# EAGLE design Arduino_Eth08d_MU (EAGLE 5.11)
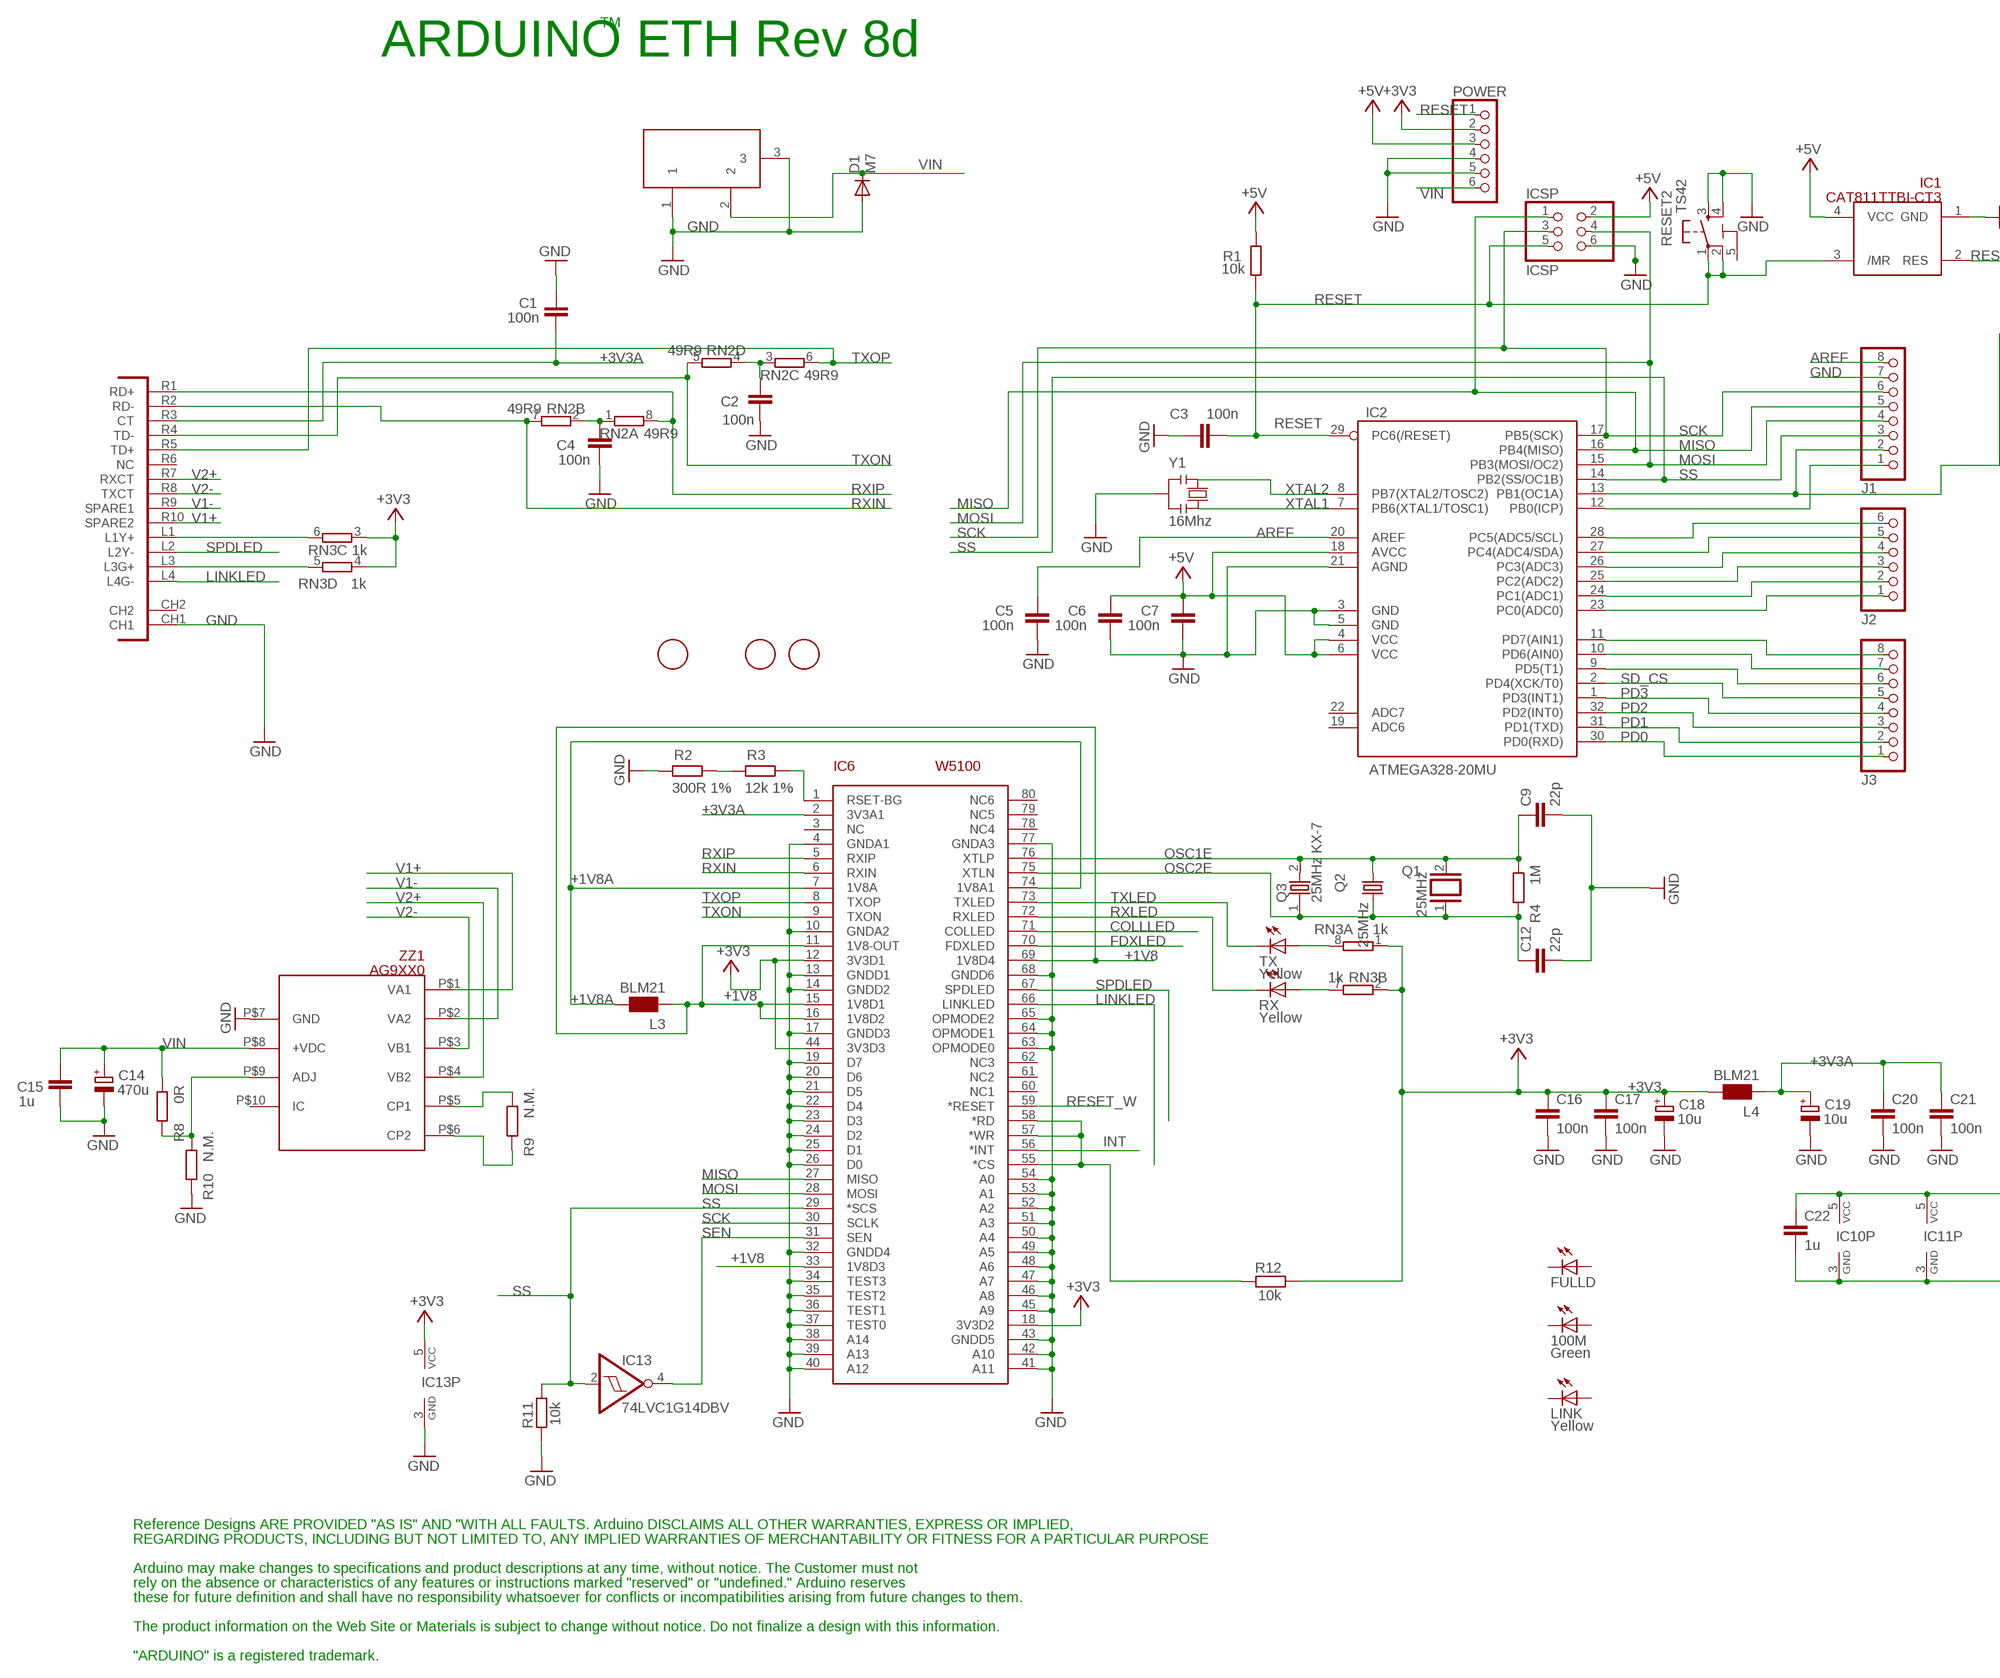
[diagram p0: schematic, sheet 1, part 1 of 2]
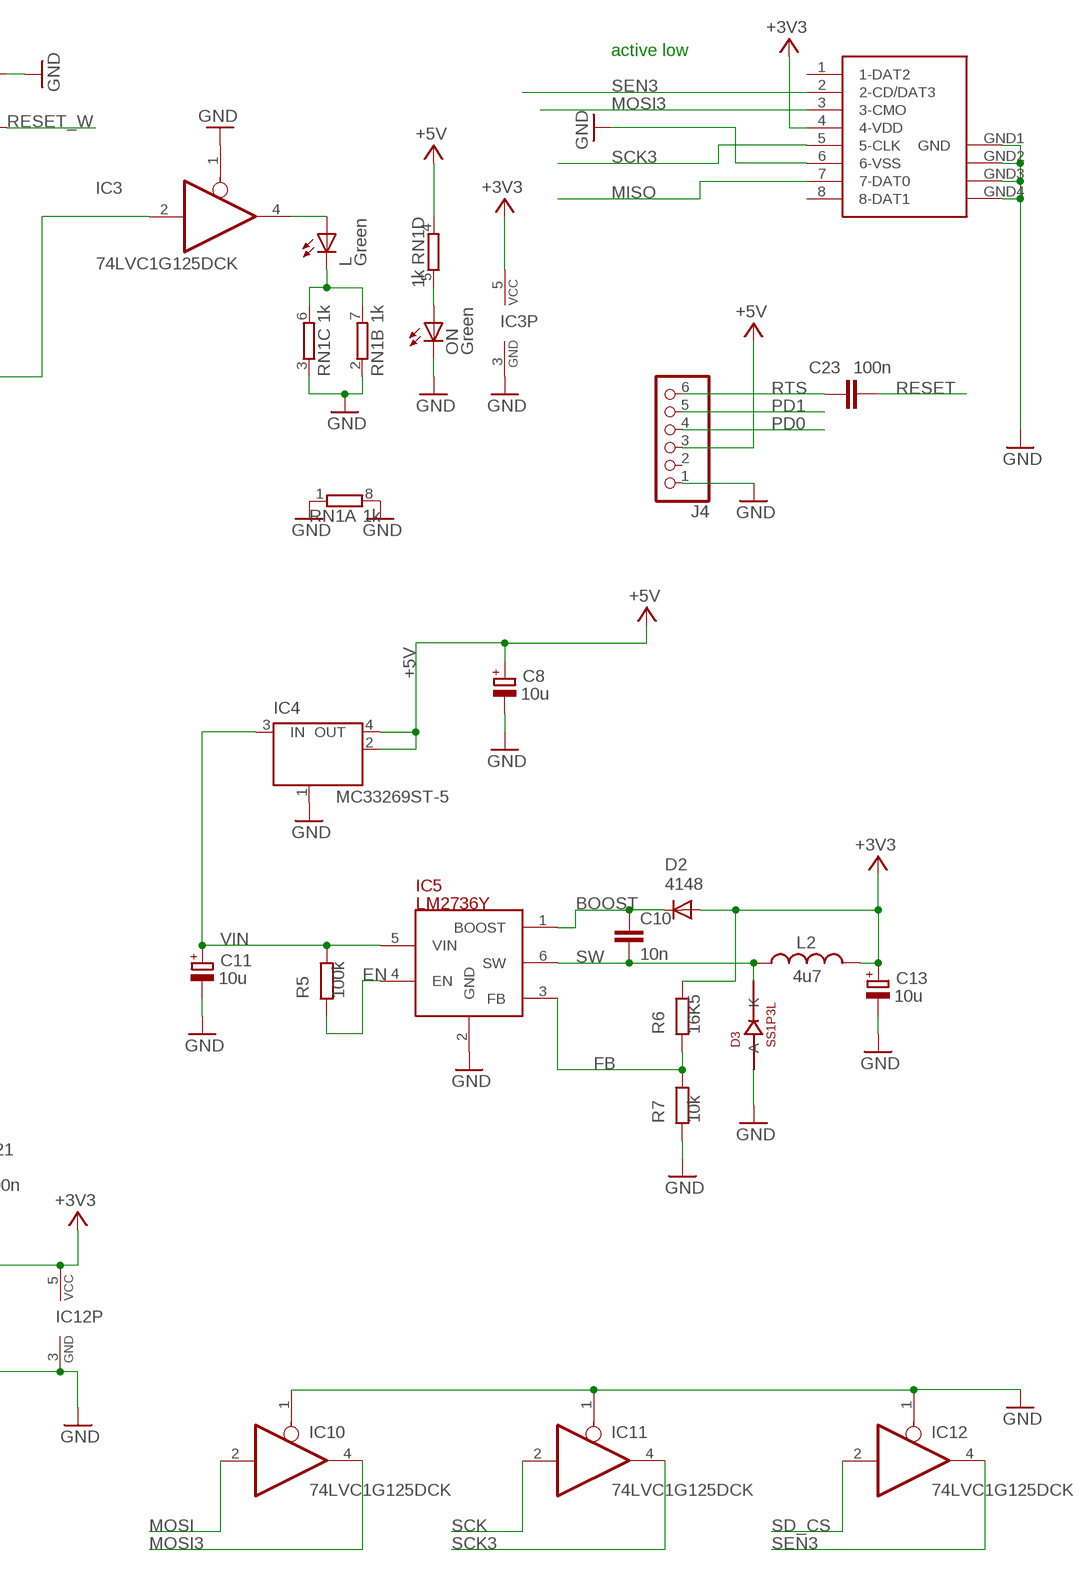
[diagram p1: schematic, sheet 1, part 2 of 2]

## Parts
100M  Green  LEDCHIPLED_0805  [CHIPLED_0805]
C1  100n  C-EUC0603  [C0603-ROUND]
C2  100n  C-EUC0603  [C0603-ROUND]
C3  100n  C-EUC0603  [C0603-ROUND]
C4  100n  C-EUC0603  [C0603-ROUND]
C5  100n  C-EUC0603  [C0603-ROUND]
C6  100n  C-EUC0603  [C0603-ROUND]
C7  100n  C-EUC0603  [C0603-ROUND]
C8  10u  CPOL-EUSMCB  [SMC_B]
C9  22p  C-EUC0603  [C0603-ROUND]
C10  10n  C-EUC0603  [C0603-ROUND]
C11  10u  CPOL-EUSMCB  [SMC_B]
C12  22p  C-EUC0603  [C0603-ROUND]
C13  10u  CPOL-EUSMCB  [SMC_B]
C14  470u  CPOL-EUD  [PANASONIC_D]
C15  1u  C-EUC0603  [C0603-ROUND]
C16  100n  C-EUC0603  [C0603-ROUND]
C17  100n  C-EUC0603  [C0603-ROUND]
C18  10u  CPOL-EUSMCB  [SMC_B]
C19  10u  CPOL-EUSMCB  [SMC_B]
C20  100n  C-EUC0603  [C0603-ROUND]
C21  100n  C-EUC0603  [C0603-ROUND]
C22  1u  C-EUC0603  [C0603-ROUND]
C23  100n  C-EUC0603  [C0603-ROUND]
D1  M7  DIODE-SMB  [SMB]
D2  4148  DIODE-MINIMELF  [MINIMELF]
D3  SS1P3L  [DO220AAL]
FULLD  LEDCHIPLED_0805  [CHIPLED_0805]
IC1  CAT811TTBI-CT3  STM812  [SOT143]
IC2  ATMEGA328-20MU  MEGA8-MI  [MLF32]
IC3  74LVC1G125DCK  [SC70-5]
IC4  MC33269ST-5  MC33269ST-3.3T3  [SOT223]
IC5  LM2736Y  [SOT23-6]
IC6  W5100  [SQFP-S-10X10-80]
IC10  74LVC1G125DCK  [SC70-5]
IC11  74LVC1G125DCK  [SC70-5]
IC12  74LVC1G125DCK  [SC70-5]
IC13  74LVC1G14DBV  [SOT23-5]
ICSP  ICSP  PINHD-2X3  [2X03]
J1  PINHD-1X8  [1X08]
J2  PINHD-1X6  [1X06]
J3  PINHD-1X8  [1X08]
J4  PINHD-1X6  [1X06]
L  Green  LEDCHIPLED_0805  [CHIPLED_0805]
L2  4u7  L-USSRR0604  [SRR0604]
L3  BLM21  WE-CBF_0805  [0805]
L4  BLM21  WE-CBF_0805  [0805]
LINK  Yellow  LEDCHIPLED_0805  [CHIPLED_0805]
ON  Green  LEDCHIPLED_0805  [CHIPLED_0805]
POWER  PINHD-1X6  [1X06]
Q1  25MHz  XTAL/S  [QS]
Q2  25MHz  CRYSTALHC49UP  [HC49UP]
Q3  25MHz KX-7  KX-7  [CRYSTAL3.2X2.5]
R1  10k  R-EU_0603-RND  [R0603-ROUND]
R2  300R 1%  R-EU_0603-RND  [R0603-ROUND]
R3  12k 1%  R-EU_0603-RND  [R0603-ROUND]
R4  1M  R-EU_0603-RND  [R0603-ROUND]
R5  100k  R-EU_0603-RND  [R0603-ROUND]
R6  16K5  R-EU_0603-RND  [R0603-ROUND]
R7  10k  R-EU_0603-RND  [R0603-ROUND]
R8  0R  R-EU_0603-RND  [R0603-ROUND]
R9  N.M.  R-EU_0603-RND  [R0603-ROUND]
R10  N.M.  R-EU_0603-RND  [R0603-ROUND]
R11  10k  R-EU_0603-RND  [R0603-ROUND]
R12  10k  R-EU_R0603  [R0603-ROUND]
RESET2  TS42  [TS42]
RN1  1k  4R-NCAY16  [CAY16]
RN2  49R9  4R-NCAY16  [CAY16]
RN3  1k  4R-NCAY16  [CAY16]
RX  Yellow  LEDCHIPLED_0805  [CHIPLED_0805]
TX  Yellow  LEDCHIPLED_0805  [CHIPLED_0805]
U$1  POE-RJ45  [POE-RJ45]
U$2  FIDUCIALMOUNT  [FIDUCIA-MOUNT]
U$4  FIDUCIALMOUNT  [FIDUCIA-MOUNT]
U$5  FIDUCIALMOUNT  [FIDUCIA-MOUNT]
X1  DC21MMX  [DC-21MM]
X2  SDCARD-15TW-8821  [SDCARD-15TW-8821]
Y1  16Mhz  RESONATORMU  [RESONATOR]
ZZ1  AG9XX0  [AG9000]

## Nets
+1V8 [power]: IC6.11(1V8-OUT) IC6.15(1V8D1) IC6.16(1V8D2) IC6.33(1V8D3) IC6.69(1V8D4) L3.1
+1V8A [power]: IC6.7(1V8A) IC6.74(1V8A1) L3.2
+3V3 [power]: C13.+ C16.1 C17.1 C18.+ C22.1 D2.A IC3.5(VCC) IC6.12(3V3D1) IC6.18(3V3D2) IC6.44(3V3D3) IC10.5(VCC) IC11.5(VCC) IC12.5(VCC) IC13.5(VCC) L2.P$2 L4.2 POWER.2 R6.1 R12.2 RN3.1 RN3.2 RN3.3 RN3.4 X2.4(4-VDD)
+3V3A [power]: C1.1 C19.+ C20.1 C21.1 IC6.2(3V3A1) L4.1 U$1.R3(CT)
+5V [power]: C6.1 C7.1 C8.+ IC1.4(VCC) IC2.4(VCC) IC2.6(VCC) IC2.18(AVCC) IC4.2(OUT) IC4.4(OUT) ICSP.2 J4.3 POWER.3 R1.2 RN1.4
AREF: C5.1 IC2.20(AREF) J1.8
BOOST: C10.1 D2.C IC5.1(BOOST)
COLLLED: IC6.71(COLLED)
EN: IC5.4(EN) R5.2
FB: IC5.3(FB) R6.2 R7.1
FDXLED: IC6.70(FDXLED)
GND [power]: C1.2 C2.1 C3.2 C4.1 C5.2 C6.2 C7.2 C8.- C9.2 C11.- C12.2 C13.- C14.- C15.1 C16.2 C17.2 C18.- C19.- C20.2 C21.2 C22.2 D1.A D3.P$2(A) IC1.1(GND) IC2.3(GND) IC2.5(GND) IC2.21(AGND) IC3.1(OE) IC3.3(GND) IC4.1(GND/ADJ) IC5.2(GND) IC6.4(GNDA1) IC6.10(GNDA2) IC6.13(GNDD1) IC6.14(GNDD2) IC6.17(GNDD3) IC6.19(D7) IC6.20(D6) IC6.21(D5) IC6.22(D4) IC6.23(D3) IC6.24(D2) IC6.25(D1) IC6.26(D0) IC6.32(GNDD4) IC6.34(TEST3) IC6.35(TEST2) IC6.36(TEST1) IC6.37(TEST0) IC6.38(A14) IC6.39(A13) IC6.40(A12) IC6.41(A11) IC6.42(A10) IC6.43(GNDD5) IC6.45(A9) IC6.46(A8) IC6.47(A7) IC6.48(A6) IC6.49(A5) IC6.50(A4) IC6.51(A3) IC6.52(A2) IC6.53(A1) IC6.54(A0) IC6.63(OPMODE0) IC6.64(OPMODE1) IC6.65(OPMODE2) IC6.68(GNDD6) IC6.77(GNDA3) IC10.1(OE) IC10.3(GND) IC11.1(OE) IC11.3(GND) IC12.1(OE) IC12.3(GND) IC13.3(GND) ICSP.6 J1.7 J4.1 ON.C POWER.4 POWER.5 R2.2 R7.2 R10.2 R11.1 RESET2.3 RESET2.4 RN1.1 RN1.2 RN1.3 RN1.8 U$1.CH1 X1.1 X1.3 X2.6(6-VSS) X2.GND1(GND) X2.GND2(GND1) X2.GND3(GND2) X2.GND4(GND3) Y1.2 ZZ1.P$7(GND)
INT: IC6.56(*INT)
LINKLED: IC6.66(LINKLED) U$1.L4(L4G-)
MISO: IC2.16(PB4(MISO)) IC6.27(MISO) ICSP.1 J1.5 X2.7(7-DAT0)
MOSI: IC2.15(PB3(MOSI/OC2)) IC6.28(MOSI) IC10.2(I) ICSP.4 J1.4
MOSI3: IC10.4(O) X2.3(3-CMO)
N$1: IC3.4(O) L.A
N$2: RN3.5 U$1.L3(L3G+)
N$3: RN3.6 U$1.L1(L1Y+)
N$4: IC2.13(PB1(OC1A)) IC3.2(I) J1.2
N$5: L.C RN1.6 RN1.7
N$8: ON.A RN1.5
N$9: RN3.8 TX.A
N$10: C2.2 RN2.3 RN2.4
N$13: IC2.9(PD5(T1)) J3.6
N$14: IC2.10(PD6(AIN0)) J3.7
N$15: IC2.11(PD7(AIN1)) J3.8
N$16: IC2.23(PC0(ADC0)) J2.1
N$17: IC2.24(PC1(ADC1)) J2.2
N$18: IC2.25(PC2(ADC2)) J2.3
N$19: IC2.26(PC3(ADC3)) J2.4
N$20: IC2.27(PC4(ADC4/SDA)) J2.5
N$21: IC2.28(PC5(ADC5/SCL)) J2.6
N$22: RN3.7 RX.A
N$29: C4.2 RN2.1 RN2.2
N$30: R2.1 R3.2
N$31: IC6.1(RSET-BG) R3.1
N$32: R9.1 ZZ1.P$5(CP1)
N$33: R9.2 ZZ1.P$6(CP2)
N$34: R8.2 R10.1 ZZ1.P$9(ADJ)
N$36: IC6.55(*CS) IC6.57(*WR) IC6.58(*RD) R12.1
OSC1E: C9.1 IC6.76(XTLP) Q1.2 Q2.1 Q3.2 R4.1
OSC2E: C12.1 IC6.75(XTLN) Q1.1 Q2.2 Q3.1 R4.2
PD0: IC2.30(PD0(RXD)) J3.1 J4.4
PD1: IC2.31(PD1(TXD)) J3.2 J4.5
PD2: IC2.32(PD2(INT0)) J3.3
PD3: IC2.1(PD3(INT1)) J3.4
RESET: C3.1 C23.1 IC1.3(/MR) IC2.29(PC6(/RESET)) ICSP.5 POWER.1 R1.1 RESET2.1 RESET2.2
RESET_W: IC1.2(RES) IC6.59(*RESET)
RTS: C23.2 J4.6
RXIN: IC6.6(RXIN) RN2.7 U$1.R2(RD-)
RXIP: IC6.5(RXIP) RN2.8 U$1.R1(RD+)
RXLED: IC6.72(RXLED) RX.C
SCK: IC2.17(PB5(SCK)) IC6.30(SCLK) IC11.2(I) ICSP.3 J1.6
SCK3: IC11.4(O) X2.5(5-CLK)
SD_CS: IC2.2(PD4(XCK/T0)) IC12.2(I) J3.5
SEN: IC6.31(SEN) IC13.4(O)
SEN3: IC12.4(O) X2.2(2-CD/DAT3)
SPDLED: IC6.67(SPDLED) U$1.L2(L2Y-)
SS: IC2.14(PB2(SS/OC1B)) IC6.29(*SCS) IC13.2(I) J1.3 R11.2
SW [power]: C10.2 D3.P$1(K) IC5.6(SW) L2.P$1
TXLED: IC6.73(TXLED) TX.C
TXON: IC6.9(TXON) RN2.5 U$1.R4(TD-)
TXOP: IC6.8(TXOP) RN2.6 U$1.R5(TD+)
V1+ [VIN]: U$1.R10(SPARE2) ZZ1.P$1(VA1)
V1- [VIN]: U$1.R9(SPARE1) ZZ1.P$2(VA2)
V2+ [VIN]: U$1.R7(RXCT) ZZ1.P$4(VB2)
V2- [VIN]: U$1.R8(TXCT) ZZ1.P$3(VB1)
VIN [VIN]: C11.+ C14.+ C15.2 D1.C IC4.3(IN) IC5.5(VIN) POWER.6 R5.1 R8.1 X1.2 ZZ1.P$8(+VDC)
WOL/IO: IC2.12(PB0(ICP)) J1.1
XTAL1: IC2.7(PB6(XTAL1/TOSC1)) Y1.3
XTAL2: IC2.8(PB7(XTAL2/TOSC2)) Y1.1
Unconnected: 100M.A 100M.C FULLD.A FULLD.C IC2.19(ADC6) IC2.22(ADC7) IC6.3(NC) IC6.60(NC1) IC6.61(NC2) IC6.62(NC3) IC6.78(NC4) IC6.79(NC5) IC6.80(NC6) J4.2 LINK.A LINK.C U$1.CH2 U$1.R6(NC) X2.1(1-DAT2) X2.8(8-DAT1) ZZ1.P$10(IC)

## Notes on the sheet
- TM
- ARDUINO ETH Rev 8d
- active low
- Reference Designs ARE PROVIDED "AS IS" AND "WITH ALL FAULTS. Arduino DISCLAIMS ALL OTHER WARRANTIES, EXPRESS OR IMPLIED,
- REGARDING PRODUCTS, INCLUDING BUT NOT LIMITED TO, ANY IMPLIED WARRANTIES OF MERCHANTABILITY OR FITNESS FOR A PARTICULAR PURPOSE
- Arduino may make changes to specifications and product descriptions at any time, without notice. The Customer must not
- rely on the absence or characteristics of any features or instructions marked "reserved" or "undefined." Arduino reserves
- these for future definition and shall have no responsibility whatsoever for conflicts or incompatibilities arising from future changes to them.
- The product information on the Web Site or Materials is subject to change without notice. Do not finalize a design with this information.
- "ARDUINO" is a registered trademark.

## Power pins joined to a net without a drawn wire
5-GND: RESET2.5(5-GND)

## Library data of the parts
100M FULLD L LINK ON RX TX = led:LED: LED
C1-C7 C9 C10 C12 C15-C17 C20-C23 = SmartPrj:C-EU: CAPACITOR, European symbol
C8 C11 C13 C14 C18 C19 = rcl:CPOL-EU: POLARIZED CAPACITOR, European symbol
D1 D2 = diode:DIODE-: DIODE
D3 = SmartPrj:SS1P3L
IC1 = SmartPrj:STM812
IC2 = idii:MEGA8: MICROCONTROLLER 8 Kbytes FLASH 1 kbytes SRAM 512 bytes EEPROM USART 6-channel 10 bit ADC 2-channel 8 bit ADC Source: avr.lbr
IC3 IC10-IC12 = 74xx-little-us:74*1G125: Single Bus Buffer Gate with 3-State Output
IC4 = linear:MC33269ST*: Adjustable Output Low Dropout Voltage Regulator 800 mA Source: http://www.onsemi.com/pub/Collateral/MC33269-D.PDF
IC5 = SmartPrj:LM2736Y
IC6 = SmartPrj:W5100
IC13 = 74xx-little-de:74*1G14: Single Schmitt-Trigger Inverter Gate
ICSP = pinhead:PINHD-2X3: PIN HEADER
J1 J3 = pinhead:PINHD-1X8: PIN HEADER
J2 J4 POWER = pinhead:PINHD-1X6: PIN HEADER
L2 = SmartPrj:L-US: INDUCTOR, American symbol
L3 L4 = wuerth-elektronik:WE-CBF: SMD EMI Suppression Ferrite Beads
Q1 = special:XTAL/S: CRYSTAL
Q2 = crystal:CRYSTAL: CRYSTAL
Q3 = SmartPrj:KX-7
R1-R12 = SmartPrj:R-EU_: RESISTOR, European symbol
RESET2 = st-mod v1.4:TS42: TS42 Dongnan Electronics Tact switch VDC 12V - 50mA
RN1-RN3 = resistor-dil:4R-N: Array Chip Resistor Source: RS Component / Phycomp
U$1 = SmartPrj:POE-RJ45
U$2 U$4 U$5 = SmartPrj:FIDUCIALMOUNT
X1 = powersupply:DC21MM
X2 = st-mod v1.3:SDCARD-15TW-8821: SD Card SDCARD 15TW 8821
Y1 = Nano_MySMD2:RESONATOR
ZZ1 = SmartPrj:AG9XX0: PoE module

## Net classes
0 default: width 0.152 mm, drill 0.61 mm, clearance 0.152 mm
1 power: width 0.152 mm, drill 0.61 mm, clearance 0.152 mm
2 VIN: width 0.61 mm, drill 0.61 mm, clearance 0.305 mm

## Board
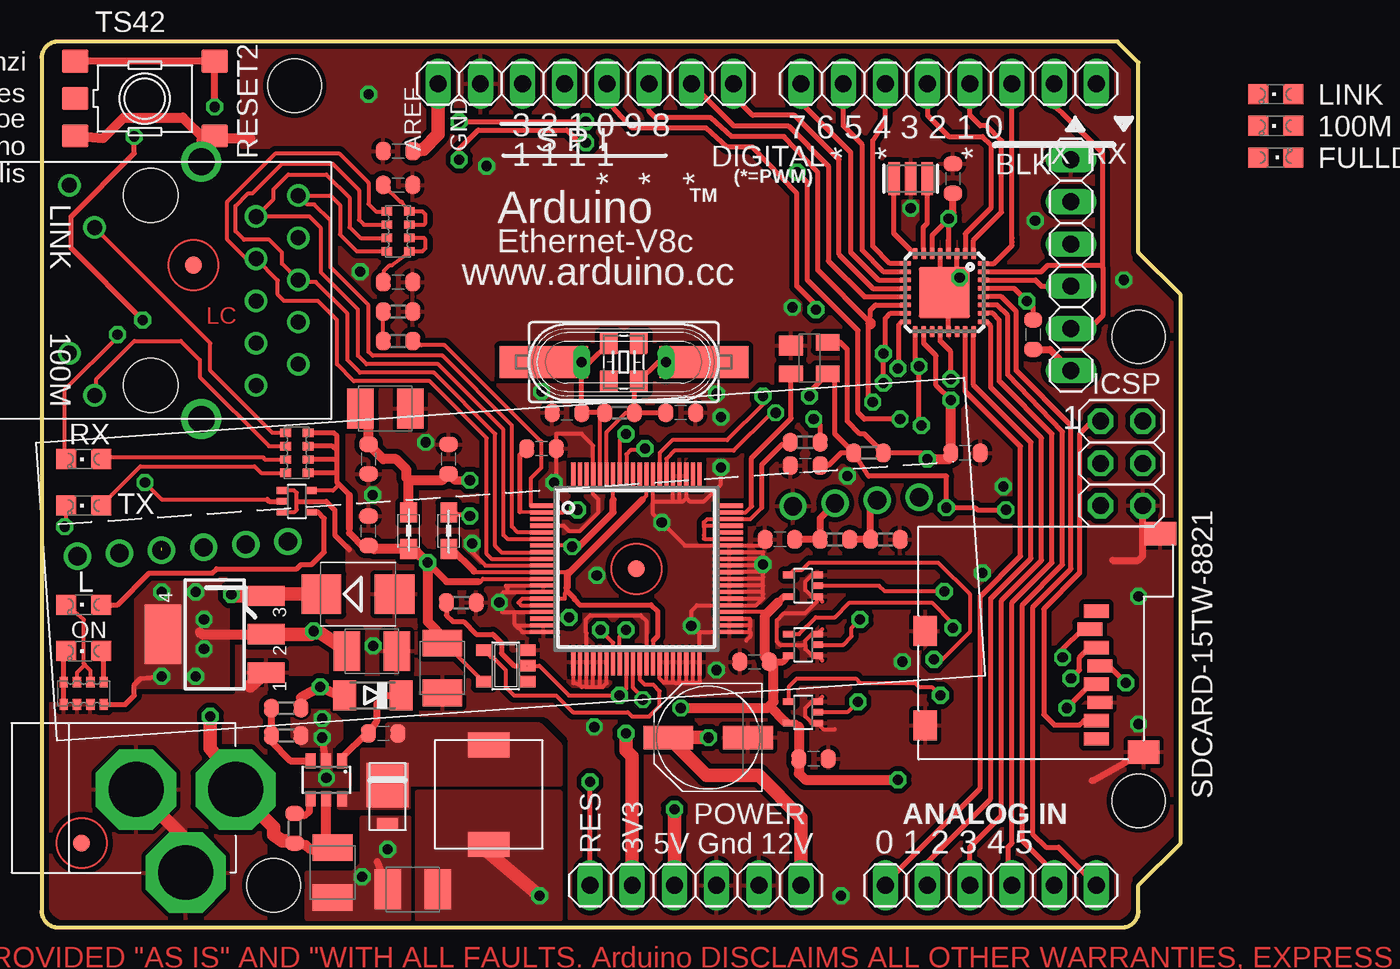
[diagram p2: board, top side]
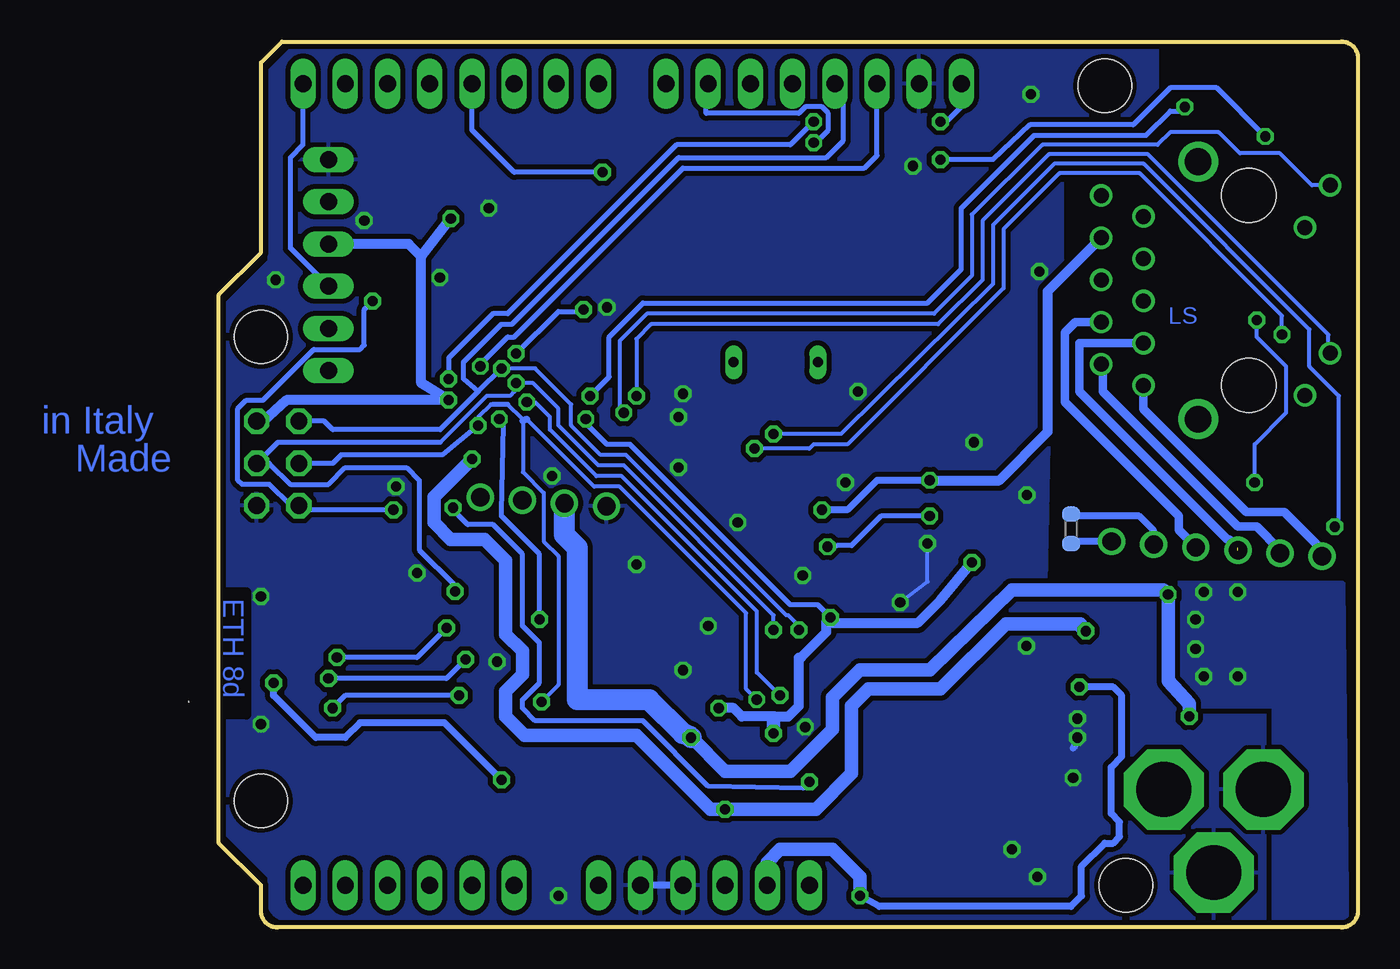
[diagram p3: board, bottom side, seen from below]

Size 68.58 x 53.34 mm. Coordinates in mm from the lower left corner, seen from the top.
Outline: 66.04,2.54 68.58,5.08 68.58,38.1 66.04,40.64 66.04,52.07 64.77,53.34 1,53.34 arc90 0,52.34 0,1 arc90 1,0 65.04,0 arc90 66.04,1 66.04,2.54
Copper layers (1*16): Top 0.035mm / dielectric 1.5mm / Bottom 0.035mm
Design rules "ArduinoDEF": minimum track width 6mil, minimum drill 12mil, track to track 5mil, track to pad 5mil, pad to pad 5mil, via to via 5mil, smd to smd 4mil, copper to edge 10mil, drill to drill 6mil, minimum pad ring 8mil, minimum via ring 8mil, stop-mask expansion 0mil, vias tented up to drill 0mil, thermal gap 10mil
Holes 3.2 mm at 66.04,35.56 66.04,7.62 15.24,50.67 13.97,2.54
bRestrict: area 66.9,12.8 to 69,20.2

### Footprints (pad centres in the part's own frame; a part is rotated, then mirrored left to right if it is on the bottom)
CHIPLED_0805 = smd 1.2 x 1.2: A 0,-1.05; C 0,1.05
C0603-ROUND = smd 0.898 x 1.1: 1 -0.889,0; 2 0.889,0
SMC_B = smd 1.6 x 2.4: + -1.5,0; - 1.5,0
PANASONIC_D = smd 3 x 1.4: + 2.4,0; - -2.4,0
SMB = smd 2.4 x 2.4: A 2.2,0; C -2.2,0
MINIMELF = smd 1.4 x 1.8: A 1.7,0; C -1.7,0
DO220AAL = smd 2.667 x 2.54: P$1 -0.7,0 | smd 0.762 x 1.27: P$2 1.65,0
SOT143 = smd 1.2 x 1.44: 1 -0.75,-1.1 | smd 1 x 1.44: 2 0.95,-1.1; 3 0.95,1.1; 4 -0.95,1.1
MLF32 = smd 0.7 x 0.3: 1 -2.35,1.75; 2 -2.35,1.25; 3 -2.35,0.75; 4 -2.35,0.25; 5 -2.35,-0.25; 6 -2.35,-0.75; 7 -2.35,-1.25; 8 -2.35,-1.75; 17 2.35,-1.75; 18 2.35,-1.25; 19 2.35,-0.75; 20 2.35,-0.25; 21 2.35,0.25; 22 2.35,0.75; 23 2.35,1.25; 24 2.35,1.75 | smd 0.3 x 0.7: 9 -1.75,-2.35; 10 -1.25,-2.35; 11 -0.75,-2.35; 12 -0.25,-2.35; 13 0.25,-2.35; 14 0.75,-2.35; 15 1.25,-2.35; 16 1.75,-2.35; 25 1.75,2.35; 26 1.25,2.35; 27 0.75,2.35; 28 0.25,2.35; 29 -0.25,2.35; 30 -0.75,2.35; 31 -1.25,2.35; 32 -1.75,2.35 | smd 3.1 x 3.1: PAD 0,0
SC70-5 = smd 0.4 x 0.7: 1 -0.65,-0.85; 2 0,-0.85; 3 0.65,-0.85; 4 0.65,0.85; 5 -0.65,0.85
SOT223 = smd 1.219 x 2.235: 1 -2.311,-3.099; 2 0,-3.099; 3 2.311,-3.099 | smd 3.6 x 2.2: 4 0,3.099
SOT23-6 = smd 0.6 x 0.9: 1 -0.95,-1.15; 2 0,-1.15; 3 0.95,-1.15; 4 0.95,1.15; 5 0,1.15; 6 -0.95,1.15
SQFP-S-10X10-80 = smd 0.25 x 1.6: 1 -3.8,-5.6; 2 -3.4,-5.6; 3 -3,-5.6; 4 -2.6,-5.6; 5 -2.2,-5.6; 6 -1.8,-5.6; 7 -1.4,-5.6; 8 -1,-5.6; 9 -0.6,-5.6; 10 -0.2,-5.6; 11 0.2,-5.6; 12 0.6,-5.6; 13 1,-5.6; 14 1.4,-5.6; 15 1.8,-5.6; 16 2.2,-5.6; 17 2.6,-5.6; 18 3,-5.6; 19 3.4,-5.6; 20 3.8,-5.6; 41 3.8,5.6; 42 3.4,5.6; 43 3,5.6; 44 2.6,5.6; 45 2.2,5.6; 46 1.8,5.6; 47 1.4,5.6; 48 1,5.6; 49 0.6,5.6; 50 0.2,5.6; 51 -0.2,5.6; 52 -0.6,5.6; 53 -1,5.6; 54 -1.4,5.6; 55 -1.8,5.6; 56 -2.2,5.6; 57 -2.6,5.6; 58 -3,5.6; 59 -3.4,5.6; 60 -3.8,5.6 | smd 1.6 x 0.25: 21 5.6,-3.8; 22 5.6,-3.4; 23 5.6,-3; 24 5.6,-2.6; 25 5.6,-2.2; 26 5.6,-1.8; 27 5.6,-1.4; 28 5.6,-1; 29 5.6,-0.6; 30 5.6,-0.2; 31 5.6,0.2; 32 5.6,0.6; 33 5.6,1; 34 5.6,1.4; 35 5.6,1.8; 36 5.6,2.2; 37 5.6,2.6; 38 5.6,3; 39 5.6,3.4; 40 5.6,3.8; 61 -5.6,3.8; 62 -5.6,3.4; 63 -5.6,3; 64 -5.6,2.6; 65 -5.6,2.2; 66 -5.6,1.8; 67 -5.6,1.4; 68 -5.6,1; 69 -5.6,0.6; 70 -5.6,0.2; 71 -5.6,-0.2; 72 -5.6,-0.6; 73 -5.6,-1; 74 -5.6,-1.4; 75 -5.6,-1.8; 76 -5.6,-2.2; 77 -5.6,-2.6; 78 -5.6,-3; 79 -5.6,-3.4; 80 -5.6,-3.8
SOT23-5 = smd 0.69 x 0.99: 1 -0.95,-1.29; 2 0,-1.29; 3 0.95,-1.29; 4 0.95,1.3; 5 -0.95,1.3
2X03 = drill 1.016 octagon: 1 -2.54,-1.27; 2 -2.54,1.27; 3 0,-1.27; 4 0,1.27; 5 2.54,-1.27; 6 2.54,1.27
1X08 = drill 1.016 long: 1 -8.89,0; 2 -6.35,0; 3 -3.81,0; 4 -1.27,0; 5 1.27,0; 6 3.81,0; 7 6.35,0; 8 8.89,0
1X06 = drill 1.016 long: 1 -6.35,0; 2 -3.81,0; 3 -1.27,0; 4 1.27,0; 5 3.81,0; 6 6.35,0
SRR0604 = smd 1.5 x 2.5: P$1 3,0; P$2 -3,0
0805 = smd 1.2 x 1: 1 -1.1,0; 2 1.1,0
QS = drill 0.61 long: 1 -2.54,0; 2 2.54,0
HC49UP = smd 5.334 x 1.93: 1 -4.826,0; 2 4.826,0
CRYSTAL3.2X2.5 = smd 1.3 x 1.1: 1 -1.15,-0.9; 2 1.15,0.9; 3 1.15,-0.9; 4 -1.15,0.9
R0603-ROUND = smd 0.898 x 1.1: 1 -0.889,0; 2 0.889,0
TS42 = smd 1.6 x 1.4: 1 -4.2,2.25; 2 4.2,2.25; 3 -4.2,-2.25; 4 4.2,-2.25; 5 -4.2,0
CAY16 = smd 0.5 x 0.65: 1 -1.2,-0.675; 2 -0.4,-0.675; 3 0.4,-0.675; 4 1.2,-0.675; 5 1.2,0.675; 6 0.4,0.675; 7 -0.4,0.675; 8 -1.2,0.675
POE-RJ45 = drill 1.6 round: CH1 13.94,7.75; CH2 13.94,-7.75 | drill 0.9 round: L1 7.51,-6.325; L2 5.99,-3.785; L3 7.51,3.785; L4 5.99,6.325; R1 19.77,5.715; R2 17.23,4.445; R3 19.77,3.175; R4 17.23,1.905; R5 19.77,0.635; R6 17.23,-0.635; R7 19.77,-1.905; R8 17.23,-3.175; R9 19.77,-4.445; R10 17.23,-5.715 | hole 3.25: 10.89,5.715; 10.89,-5.715
FIDUCIA-MOUNT = smd 1.016 x 1.016: P$1 0,0
DC-21MM = drill 3.302 pad 4.826 octagon: 1 -5.08,-3.353; 2 -0.076,-6.35; 3 -0.076,-0.356
SDCARD-15TW-8821 = smd 0.8 x 1.5: 1 0,0; 2 1.1,-0.4; 3 2.2,0; 4 3.3,0.2; 5 4.4,0; 6 5.5,0.2; 7 6.6,0; 8 7.7,0 | smd 1.4 x 1.9: GND1 -4.66,3.85; GND2 8.49,2.85 | smd 1.8 x 1.4: GND3 1.19,-10.3; GND4 6.89,-10.3
RESONATOR = smd 0.7 x 2: 1 -1,0; 2 0,0; 3 1,0
AG9000 = drill 1.1 round: P$1 0,0; P$2 2.54,0; P$3 5.08,0; P$4 7.62,0; P$5 10.16,0; P$6 12.7,0; P$7 43.18,0; P$8 45.72,0; P$9 48.26,0; P$10 50.8,0

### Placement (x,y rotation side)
100M  not placed on the board
C1  30.1,28.83 0 top
C2  21.46,44.7 180 top
C3  45.97,27.81 180 top
C4  21.46,38.86 180 top
C5  21.46,46.74 180 top
C6  55.63,28.57 0 top
C7  54.86,45.09 90 top
C8  19.89,16.64 0 top
C9  31.62,30.99 180 top
C10  20.57,11.68 0 top
C11  17.53,3.3 270 top
C12  38.48,30.99 0 top
C13  24.13,15.62 270 top
C14  40.13,11.43 180 top
C15  44.45,23.37 0 top
C16  42.93,16 180 top
C17  19.68,23.88 90 top
C18  22.35,2.29 180 top
C19  20.7,31.24 0 top
C20  19.68,28.19 270 top
C21  24.51,28.19 90 top
C22  46.48,10.16 0 top
C23  59.69,35.69 270 top
D1  19.05,20.07 0 top
D2  19.94,13.97 180 top
D3  20.83,7.87 270 top
FULLD  not placed on the board
IC1  46.23,34.29 270 top
IC2  54.36,38.23 270 top
IC3  15.37,25.65 270 top
IC4  10.41,17.65 90 top
IC5  17.14,8.89 180 top
IC6  35.81,21.59 270 top
IC10  45.85,20.57 90 top
IC11  45.85,12.95 90 top
IC12  45.85,17.02 90 top
IC13  27.94,15.75 90 top
ICSP  65.02,27.94 270 top
J1  32.77,50.8 180 top
J2  57.15,2.54 0 top
J3  54.61,50.8 180 top
J4  61.98,39.88 270 top
L  2.54,19.43 90 top
L2  26.92,8 90 top
L3  24.51,23.88 90 top
L4  22.1,23.88 270 top
LINK  not placed on the board
ON  2.54,16.64 90 top
POWER  39.37,2.54 0 top
Q1  35.05,34.04 180 top
Q2  35.05,34.04 0 top
Q3  35.05,34.04 90 top
R1  49.78,28.57 0 top
R2  21.46,37.08 0 top
R3  21.46,35.31 180 top
R4  34.8,30.99 0 top
R5  15.24,5.97 90 top
R6  14.73,13.21 180 top
R7  14.73,11.56 0 top
R8  47.75,23.37 0 top
R9  17.27,24 270 bottom
R10  50.8,23.37 0 top
R11  25.27,19.56 180 top
R12  45.97,29.21 0 top
RESET2  6.22,49.91 0 top
RN1  2.54,14.1 0 top
RN2  21.46,41.91 90 top
RN3  15.37,28.57 90 top
RX  2.54,28.19 90 top
TX  2.54,25.4 90 top
U$1  -4.32,38.35 0 top
U$2  9.14,39.88 0 top
U$4  35.81,21.59 0 top
U$5  2.41,5.08 0 top
X1  5.33,8.38 90 top
X2  63.5,19.05 270 top
Y1  52.32,45.09 0 top
ZZ1  2.16,22.35 4 top

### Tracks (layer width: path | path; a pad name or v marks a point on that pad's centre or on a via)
+1V8
  Top 0.254: 31.62,20.45 31.59,20.3 31.5,20.07 31.5,19.79 IC6.15 28.93,19.79 28.7,19.56 28.87,19.39 IC6.16 | 36.81,17.26 IC6.33 | 26.04,21.46 26.11,21.39 IC6.11 31.7,21.39 31.75,21.34 | IC6.69 36.41,26 36.16,25.75
  Top 0.305: 31.59,20.3 32.08,19.81 32.08,19.73 32.38,19.43 36.7,19.43 37.08,19.05 37.08,17.53 36.81,17.26
  Top 0.406: 31.62,20.45 31.62,21.34 31.75,21.34 36.16,25.75 | 26.04,21.46 24.64,22.86 24.55,22.86 L3.1
+1V8A  (via drill 0.61)
  Top 0.254: IC6.7 31.62,22.99 31.88,22.99 | 34.41,25.74 IC6.74
  Top 0.305: L3.2 v25.78,24.77
  Top 0.406: 31.88,22.99 v31.94,22.92 32.35,22.92 34.41,24.99 34.41,25.74
  Bottom 0.305: v25.78,24.77 28.7,24.77 30.48,22.99 31.37,22.99 v31.94,22.92
+3V3  (via drill 0.61)
  Top 0.254: IC6.18 31.57,18.59 v31.75,18.67 | IC6.12 26.58,20.99 26.42,20.83 | IC13.5 26.6,14.8 24.64,16.76 24.38,16.74 C13.+ | IC6.44 43.63,18.99 43.56,18.8 | 44.18,14.34 44.18,14.37 44.13,14.41 | IC3.5 17.54,26.3 17.91,26.67
  Top 0.305: v46.48,30.61 46.86,30.23 R12.2 | 44.07,14.22 44.18,14.34 | 44.32,19.56 44.39,19.62 | C16.1 43.88,16.07 | X2.4 64.26,15.75 v65.28,14.73 | 18.53,23.74 18.54,24 | RN3.3 17.51,28.98 17.78,28.7 | 17.78,27.43 17.78,26.8 17.91,26.67 18.54,26.04 | 17.78,27.43 17.78,28.07 | 17.78,28.07 17.78,28.7 | RN3.1 17.72,27.38 17.78,27.43 | RN3.2 17.67,28.18 17.78,28.07 | RN3.4 17.6,29.77 17.78,29.59 17.78,28.7 | 26.29,20.83 26.42,20.83
  Top 0.406: L4.2 21.93,22.9 | 44.07,16 C16.1 44.63,16 IC12.5 | 44.39,19.62 44.69,19.92 IC10.5 | 18.54,24 18.54,26.04 | C17.1 19.41,22.86 18.53,23.74 | 26.29,20.83 24.38,20.83 v23.24,21.97 | 44.77,12.38 44.85,12.3 IC11.5 45.39,12.3 45.59,12.1
  Top 0.61: C13.+ 24.36,17.3 23.24,18.41 v23.24,21.97 22.56,22.65 L4.2 20.02,22.78 C17.1 | v51.56,8.89 45.97,8.89 45.59,9.27 C22.1 45.59,12.1 | 44.32,19.56 43.56,18.8 43.56,16.26 C16.1 | v38.48,13.21 43.69,13.21 43.81,13.34 | 44.07,16 44.07,14.22 44.07,13.59 43.81,13.34 | 43.81,13.34 44.77,12.38 | R6.1 15.62,13.84 v16.76,14.48 17.65,14.1 D2.A
  Top 0.813: v29.97,1.91 26.67,4.7 | POWER.2 35.56,10.29 35.18,10.67 v35.18,11.68
  Bottom 0.305: v31.75,18.67 32.51,19.43 34.16,19.43 43.81,29.08 45.21,29.08 46.48,30.35 v46.48,30.61
  Bottom 0.406: v16.76,14.48 14.73,14.48 14.22,13.97 14.22,10.29 14.86,9.65 14.86,6.86 14.35,6.35 14.35,5.46 14.73,5.08 15.24,5.08 16.64,3.68 16.64,1.91 17.27,1.27 28.83,1.27 v29.97,1.91 | v65.28,14.73 65.28,13.97 62.74,11.43 60.96,11.43 60.07,12.32 54.99,12.32 v51.56,8.89
  Bottom 0.61: v23.24,21.97 25.15,19.68 26.5,18.34 31.67,18.34 v31.75,18.67 32,18.41 32,17.78 33.53,16.26 33.66,16.26 33.66,13.34 34.29,12.7 35.05,12.7 | 35.05,12.7 37.08,12.7 37.59,13.21 v38.48,13.21 | 35.18,12.57 35.05,12.7
  Bottom 0.813: v29.97,1.91 29.97,3.05 31.62,4.7 34.8,4.7 35.56,3.94 POWER.2 | v35.18,11.68 35.18,12.57
  pour Top (no thermals): 31.24,8.13 22.61,8.13 22.61,0.51 31.24,0.51
+3V3A  (via drill 0.61)
  Top 0.254: 28.8,25.02 31.4,24.99 IC6.2 32.5,24.99 32.16,24.99 32.18,25.02
  Top 0.305: 28.8,25.02 28.8,28.47 C1.1
  Top 0.406: v32.26,25.15 32.18,25.02
  Top 0.508: v25.78,26.92 24.89,26.92 C21.1
  Top 0.61: L4.1 22.1,26.95 | 22.1,26.95 24.15,26.95 C21.1 | C19.+ 19.68,30.76 C20.1 20.57,28.19 21.34,28.19 21.97,27.56 21.97,27.07 22.1,26.95
  Bottom 0.406: v32.26,25.15 30.73,25.15 28.96,26.92 v25.78,26.92
  Bottom 0.61: U$1.R3 18.67,38.31 18.67,29.84 21.59,26.92 v25.78,26.92
+5V  (via drill 0.61, 0.61 pad 1.02)
  Top 0.305: IC1.4 48.07,35.24 48.51,34.8 48.51,30.48 49.28,29.72 49.53,29.72 R1.2 52.96,28.57 v53.34,28.19 53.34,28.32 | 54.61,41.41 IC2.4 v54.61,42.67 53.61,41.67 IC2.6 | v7.24,15.11 5.97,14.99 5.59,14.61 5.59,13.97 5.04,13.42 RN1.4 | IC2.18 53.11,35.16 53.85,34.42 53.85,32.64 v54.74,31.75
  Top 0.406: C7.1 54.86,43.05 v54.61,42.67 | 54.61,28.19 C6.1
  Top 0.61: IC4.2 9.65,17.65 9.53,17.78 | C6.1 v54.74,31.75 | v53.34,28.19 54.61,28.19
  Top 0.813: v38.1,7.11 POWER.3 | C8.+ 16.64,17.81 v16.39,17.84 16.2,17.65 IC4.2
  Bottom 0.61: 56.39,40.39 56.39,32.77 v54.74,31.75 64.52,31.75 65.91,30.48 ICSP.2 | 56.39,40.39 v54.61,42.67 | J4.3 57.15,41.15 56.39,40.39
  Bottom 0.813: 16.71,18.29 v16.39,17.84 16.84,18.29 21.21,18.29 25.15,14.35 29.46,14.35 30.48,13.34 30.48,9.27 32.64,7.11 v38.1,7.11 38.99,7.11 43.43,11.56 50.16,11.56 51.31,12.7 51.31,14.22 50.29,15.24 50.29,16.64 51.31,17.65 51.31,22.1 52.58,23.37 54.61,23.37 55.63,24.38 55.63,25.91 v53.34,28.19
  other vias: 9.27,20.19 7.24,20.19 9.27,15.11 9.78,18.54 9.78,16.76
  pour Top (isolate 0.305, no thermals): 5.71,20.95 11.18,21.08 11.18,14.48 5.71,14.48
  pour Bottom (isolate 0.305, no thermals): 0.89,20.7 10.92,20.7 10.92,13.34 5.08,13.34 5.08,-0.64 0.64,-0.64
AREF  (via drill 0.61, 0.61 pad 1.02)
  Top 0.305: v25.15,48.51 v32.77,48.51 | IC2.20 54.11,35.3 54.74,34.67 v54.74,33.02
  Top 0.813: J1.8 23.88,47.75 22.99,46.86 C5.1
  Bottom 0.305: v32.77,48.51 34.16,47.12 41.02,47.12 51.18,36.96 52.07,36.96 54.74,34.29 v54.74,33.02 | v25.15,48.51 24.77,48.51 23.88,49.4 J1.8 | J1.8 23.88,51.18 24,51.31 24,50.93 J1.8
BOOST
  Top 0.305: 18.09,10.09 18.16,10.16 18.16,10.29
  Top 0.406: D2.C 20.7,13.97 20.19,13.46 20.19,12.45 C10.1 19.56,11.68 18.16,10.29 | IC5.1 18.09,10.09
EN
  Top 0.406: R5.2 15.82,6.73 16.13,6.99 16.13,7.67 IC5.4
FB
  Top 0.406: R6.2 R7.1 13.84,11.18 14.98,10.04 IC5.3
GND  (via drill 0.61)
  Top 0.254: IC6.4 31.44,24.19 31.75,23.88 32.41,23.88 33.53,24.99 33.53,25.78 33.21,26.09 IC6.77 33.21,29.02 32.51,29.72 30.99,29.72 C1.2 30.99,26.92 v30.86,26.8 | 28.45,18.99 27.75,18.99 v27.56,19.56 27.81,20.19 28.06,20.19 | 28.45,18.99 IC6.17 | IC6.13 27.96,20.59 27.94,20.57 28.06,20.45 28.06,20.19 | 28.06,20.19 IC6.14 | 28.55,18.19 IC6.19 | 28.55,18.19 28.45,18.29 28.45,18.99 | IC6.20 28.95,17.79 28.55,18.19 | IC6.26 34.01,14.71 33.78,14.48 33.53,14.48 | 32.77,14.48 32.51,14.48 32.41,14.58 | 32.77,14.48 33.27,14.48 | 33.27,14.48 33.53,14.48 | IC6.21 32.01,14.72 32.41,14.58 | 32.41,14.58 IC6.22 | 32.77,14.48 32.81,14.53 IC6.23 32.81,17.73 32.77,17.78 32.77,18.54 33.02,18.8 36.07,18.8 36.41,18.45 IC6.32 | IC6.24 33.21,14.54 33.27,14.48 | IC6.25 33.61,14.56 33.53,14.48 | v39.12,18.16 39.61,17.66 IC6.40 39.62,15.98 39.62,14.73 39.12,14.73 | 37.59,14.73 37.47,14.73 37.21,14.99 IC6.34 | 38.1,14.73 37.59,14.73 | 38.1,14.73 38.35,14.73 | 38.35,14.73 38.86,14.73 | 38.86,14.73 39.12,14.73 | IC6.35 37.61,14.75 37.59,14.73 | IC6.36 38.01,14.82 38.1,14.73 | IC6.37 38.41,14.79 38.35,14.73 | IC6.38 38.81,14.78 38.86,14.73 | IC6.39 39.21,14.83 39.12,14.73 | 42.66,17.79 IC6.41 39.49,17.79 v39.12,18.16 | 42.66,17.79 42.67,17.78 42.67,17.53 42.42,17.27 | 42.66,17.79 42.67,18.29 | 42.67,18.29 42.67,18.54 42.62,18.59 IC6.43 | IC6.42 42.57,18.19 42.67,18.29 | 43.3,22.99 IC6.54 38.73,22.99 v37.34,24.38 36.81,24.91 36.81,25.65 | v43.43,21.84 43.43,22.61 43.42,22.59 IC6.53 | 43.43,20.07 43.43,19.81 43.41,19.79 | 43.41,19.79 43.01,19.39 IC6.45 39.46,19.39 39.12,19.05 v39.12,18.16 | 43.43,20.07 43.43,20.57 | 43.43,20.57 43.43,21.08
  Top 0.254: 43.43,21.08 43.43,21.34 | 43.43,21.34 v43.43,21.84 | IC6.52 43.34,22.19 v43.43,21.84 | IC6.51 43.38,21.79 v43.43,21.84 | IC6.50 43.38,21.39 43.43,21.34 | IC6.49 43.34,20.99 43.43,21.08 | IC6.48 43.42,20.59 43.43,20.57 | IC6.47 43.31,20.19 43.43,20.07 | 43.41,19.79 IC6.46 | 36.81,25.65 IC6.68 | 38.81,25.86 IC6.63 | 38.81,25.86 38.61,25.65 38.35,25.65 | 36.81,25.65 38.1,25.65 | 38.1,25.65 38.35,25.65 | IC6.64 38.41,25.71 38.35,25.65 | IC6.65 38.01,25.74 38.1,25.65 | v40.89,27.69 40.89,26.67 39.88,25.65 39.02,25.65 38.81,25.86 | IC6.10 26.72,21.79 25.91,22.61 v25.91,23.11 | 47,19.62 IC10.1 46.37,19.92 45.97,20.32 45.97,20.83 46.37,21.22 IC10.3 | 47,17.97 IC12.3 46.37,17.67 45.97,17.27 45.97,17.02 | 47,16.07 IC12.1 46.37,16.37 45.97,16.76 45.97,17.02 | 47,13.9 IC11.3 46.37,13.6 45.97,13.21 45.97,12.7 46.37,12.3 IC11.1 47.06,11.94 47.75,11.94 | 46.67,19.62 45.97,18.92 44.7,18.92 44.27,18.49 44.27,17.2 44.45,17.02 45.97,17.02 | IC3.1 15.22,26.3 15.37,26.16 15.37,25.65 15.37,25.15 15.24,25.02 14.53,25.02 IC3.3
  Top 0.305: 18.54,22.73 17.65,23.62 17.65,25.15 17.14,25.65 15.37,25.65 | RN1.1 RN1.8 1.34,16.49 ON.C | IC2.21 54.61,38.45 v55.27,39.12 | IC2.3 55.11,39.28 v55.27,39.12 | IC2.5 54.1,39.24 54.23,39.12 v55.27,39.12
  Top 0.406: X1.3 5.69,8.48 | IC5.2 v16.89,11.43 | C11.- 17.8,1.68 | C18.- 20.22,3.96 | ICSP.6 66.29,22.35 66.04,22.1 64.47,22.1 | 63.25,8.84 X2.GND2
  Top 0.61: RESET2.3 3.72,47.53 4.95,48.77 8.51,48.77 9.78,47.5 9.78,47.53 | 9.78,47.53 RESET2.4 | U$1.CH1 9.62,47.38 9.78,47.53 | 9.78,47.53 12.54,47.53 12.57,47.5
  Top 0.813: X1.1 8.69,5.31 X1.3 5.71,8.33 | 12.57,14.53 IC4.1
  Bottom 0.254: v25.91,23.11 25.91,20.83 v27.56,19.56
  Bottom 0.406: POWER.4 POWER.5 | v16.89,11.43 17.14,10.79
  other vias: 23.11,29.21 19.3,3.05 20.83,4.7 16.89,12.57 17.14,9.02 66.04,12.24 33.43,21.18 40.64,15.49 33.27,12.06 19.96,16.94 57.91,26.54 59.82,42.55 40.89,30.73 66.04,19.94 48.13,1.91 19.94,26.04 19.18,39.5 26.8,45.85 19.68,50.16 30.1,32.26 45.21,37.34 48.51,27.18 52.32,43.31 40.64,32.13 51.82,16 56.64,21.34 65.15,38.99
  pour Bottom (isolate 0.406, no thermals): 14.48,15.24 23.24,15.24 24.51,13.97 24.51,13.72 30.48,13.59 30.48,0.64 14.48,0.76
  pour Top (no thermals): 16,3.3 18.8,3.3 19.3,3.81 19.3,6.6 22.1,6.6 22.1,0.51 16,0.51
  pour Top (no thermals): 15.75,8.51 15.75,9.27 16.89,9.27 16.89,10.92 15.68,10.92 15.11,11.49 15.11,12.95 15.24,13.08 17.4,13.08 18.03,12.45 18.03,11.37 17.59,10.92 17.4,10.92 17.4,9.27 18.54,9.27 18.54,8.51
  pour Top (isolate 0.305, rank 2): 0.51,13.46 5.71,13.46 5.71,20.95 18.41,20.95 18.41,37.34 17.27,37.34 17.27,46.99 12.06,46.99 12.06,53.47 64.26,52.83 65.53,51.56 65.53,40.13 68.07,37.59 68.07,5.59 65.53,3.05 65.53,1.51 arc-90 64.53,0.51 31.75,0.51 31.75,11.43 30.48,12.7 22.86,12.7 22.86,15.24 14.46,15.24 13.46,14.24 13.46,0.51 1.51,0.51 arc-90 0.51,1.51
  pour Bottom (isolate 0.305, rank 2): 17.78,46.99 12.06,46.99 12.06,52.83 64.26,52.83 65.53,51.56 65.53,40.13 68.07,37.59 68.07,5.59 65.53,3.05 65.53,1.51 arc-90 64.53,0.51 1.51,0.51 0.51,1.51 0.76,20.83 18.8,20.7 18.41,37.47 17.78,37.47
LINKLED  (via drill 0.61)
  Top 0.254: IC6.66 37.61,28.22 38.1,28.7 41.66,28.7 43.81,30.86 v44.2,30.99
  Bottom 0.254: v44.2,30.99 44.45,31.24 44.45,35.31 42.8,36.96 25.53,36.96 23.24,39.24 23.24,42.93 18.99,47.12 12.06,47.12 11.3,47.88 8.38,47.88 7.11,46.61 4.7,46.61 2.77,44.68 U$1.L4
MISO  (via drill 0.61)
  Top 0.254: IC6.27 34.41,17.14 v33.66,17.91
  Top 0.305: ICSP.1 63.25,30.48 62.48,29.72 62.48,21.34 60.33,19.18 60.33,12.83 60.96,12.19 62.48,12.19 62.74,12.45 X2.7 | IC2.16 51.8,36.48 51.61,36.27 51.61,33.74 v51.56,33.66
  Bottom 0.254: v33.66,17.91 33.66,18.16 34.29,18.8 34.42,18.8 44.07,28.45 45.59,28.45 47.37,30.23 47.37,31.5 49.53,33.66 v51.56,33.66
  Bottom 0.305: J1.5 31.5,50.42 30.99,49.91 30.99,47.37 32,46.35 40.89,46.35 50.93,36.32 51.56,36.32 53.85,34.04 53.85,33.02 52.96,32.26 | ICSP.1 62.23,30.48 61.72,29.97 55.24,29.97 52.96,32.26 | v51.56,33.66 52.96,32.26
MOSI  (via drill 0.61)
  Top 0.254: v35.18,17.91 34.8,17.53 34.8,16.01 IC6.28 | IC10.2 50.42,20.57 50.76,20.23 v54.36,20.23
  Top 0.305: J1.4 34.04,49.78 35.56,48.13 40.01,48.13 41.27,46.99 42.8,46.99 45.47,44.2 45.47,38.61 46.61,37.47 v46.61,37.21 | v54.36,20.23 54.36,20.32 | IC2.15 51.12,36.98 50.8,36.66 50.8,34.67 v50.67,34.54 v50.67,32.77
  Bottom 0.254: v35.18,17.91 35.18,18.8 44.2,27.81 45.72,27.81 48.13,30.23 48.13,31.24 49.66,32.77 v50.67,32.77 50.8,32.26 51.05,32 52.45,32 55.24,29.21
  Bottom 0.305: v54.36,20.23 54.4,20.61 56.52,22.73 56.52,26.92 57.28,27.69 60.96,27.69 61.98,26.67 64.26,26.67 65.53,27.94 ICSP.4 65.02,29.21 55.24,29.21 | v46.61,37.21 46.74,37.08 48.13,37.08 v50.67,34.54
MOSI3  (via drill 0.61)
  Top 0.254: v53.72,16.13 54.23,16.13 55.88,17.78 55.88,20.07 53.98,21.97 46.23,21.97 45.78,21.52 45.3,21.52 IC10.4
  Top 0.305: X2.3 63.08,16.85 62.48,16.26 62.48,15.49 v61.98,14.99
  Bottom 0.305: v61.98,14.99 54.86,14.99 v53.72,16.13
N$1
  Top 0.305: IC3.4 16.65,25 17.02,24.64 17.02,22.61 16.26,21.84 15.62,21.84 15.37,21.59 10.54,21.59 10.29,21.34 6.48,21.34 4.57,19.43 L.A
N$2
  Top 0.254: U$1.L3 10.16,35.17 10.16,33.53 13.91,29.77 RN3.5
N$3
  Top 0.254: U$1.L1 3.3,32.14 3.3,33.02 5.59,35.31 8.38,35.31 9.53,34.16 9.53,33.15 13.7,28.98 RN3.6
N$4  (via drill 0.61)
  Top 0.254: 13.59,25.78 7.24,25.78 v6.22,26.8
  Top 0.305: IC2.13 49.53,37.98 47.37,40.13 47.37,45.85 44.96,48.26 41.66,48.26 J1.2 | IC3.2 13.72,25.65 13.59,25.78 | v5.59,47.62 5.59,46.61 1.78,42.8 1.78,40.89 v6.1,36.58 | v25.15,46.23 25.15,46.86 26.29,48.01 31.62,48.01 32.38,47.24 v32.77,47.24
  Bottom 0.254: v6.22,26.8 6.22,29.08 4.32,30.99 4.32,33.78 6.1,35.56 6.1,36.07
  Bottom 0.305: v5.59,47.62 8.51,50.55 11.3,50.55 13.53,48.32 19.75,48.32 21.97,46.23 v25.15,46.23 | 6.1,36.07 v6.1,36.58 | J1.2 39.24,50.67 39.24,49.02 33.66,49.02 33.27,49.4 32.26,49.4 31.88,49.02 31.88,48.01 32.64,47.24 v32.77,47.24
N$5
  Top 0.254: L.C 1.65,19.3 2.54,18.54 2.54,15.88 2.6,15.81 | RN1.7 2.14,15.35 2.6,15.81 | RN1.6 2.94,15.47 2.6,15.81
N$8
  Top 0.305: RN1.5 3.74,16.49 ON.A
N$9
  Top 0.254: TX.A 5.95,27.76 12.83,27.76 13.21,27.38 RN3.8
N$10
  Top 0.254: RN2.3 23.01,42.31 23.11,42.42 23.11,42.93 22.93,43.11 RN2.4 21.69,43.69 21.59,43.69 C2.2
N$13
  Top 0.305: J3.6 50.8,48.51 50.04,47.37 50.04,41.02 51.08,39.98 IC2.9
N$14
  Top 0.305: IC2.10 50.69,39.48 49.4,40.77 49.4,47.12 48.26,48.26 J3.7
N$15
  Top 0.305: 45.72,51.21 J3.8 45.72,49.66 48.72,46.66 48.72,40.64 50.38,38.98 IC2.11
N$16
  Top 0.305: J2.1 50.8,2.67 56.52,8.38 56.52,19.94 58.93,22.35 58.93,28.96 55.61,32.28 IC2.23
N$17
  Top 0.305: J2.2 53.34,3.94 57.15,7.75 57.15,19.81 59.56,22.23 59.56,29.21 56.11,32.67 IC2.24
N$18
  Top 0.305: J2.3 55.88,4.83 57.78,6.73 57.78,19.68 60.2,22.1 60.2,29.46 57.15,32.51 57.15,36.2 56.87,36.48 IC2.25
N$19
  Top 0.305: J2.4 58.17,2.79 58.17,4.83 58.42,5.08 58.42,19.56 60.83,21.97 60.83,29.72 57.66,32.89 57.66,36.58 57.26,36.98 IC2.26
N$20
  Top 0.305: J2.5 60.96,3.3 59.05,5.21 59.05,19.43 61.47,21.84 61.47,29.84 58.17,33.27 58.17,36.83 57.52,37.48 IC2.27
N$21
  Top 0.305: J2.6 61.21,4.83 60.45,4.83 59.69,5.59 59.69,19.3 61.98,21.59 61.98,30.23 58.67,33.53 58.67,37.08 57.78,37.98 IC2.28
N$22
  Top 0.254: 3.68,28.19 RX.A 4.1,28.32 13.34,28.32 13.44,28.18 RN3.7
N$29
  Top 0.254: RN2.2 23.01,41.51 23.11,41.4 23.11,40.89 22.93,40.71 RN2.1 22.1,40.64 21.08,39.88 20.95,39.88 20.61,39.54 C4.2
N$30
  Top 0.254: R3.2 R2.1
N$31
  Top 0.254: R3.1 22.86,35.05 24.26,35.05 30.04,29.27 30.1,29.27 30.1,27.69 29.46,27.05 29.46,25.4 29.47,25.39 IC6.1
N$32
  Bottom 0.406: R9.1 17.14,24.77 13.17,24.77 12.29,23.89 ZZ1.P$5
N$33
  Bottom 0.406: ZZ1.P$6 17.15,23.24 R9.2
N$34
  Top 0.406: R8.2 R10.1 49.91,25.33 ZZ1.P$9
N$36
  Top 0.254: 43.36,25.27 42.67,24.59 IC6.58 40.08,24.59 39.88,24.38 39.88,24.13 | 39.9,23.39 IC6.55 | 39.88,23.62 39.9,23.39 | 39.88,24.13 39.88,23.62 | 39.88,23.62 39.88,23.41 39.9,23.39 | IC6.57 39.94,24.19 39.88,24.13
  Top 0.305: 43.36,25.27 43.36,27.86 44.58,29.08 44.83,29.08 R12.1
OSC1E
  Top 0.254: IC6.76 33.61,30.69 R4.1
  Top 0.305: Q1.2 Q2.1 | Q1.2 33,34.04 Q3.2 | Q1.2 C9.1 R4.1
OSC2E
  Top 0.254: IC6.75 34.01,29.82 35.18,30.99 R4.2
  Top 0.305: Q2.2 Q1.1 37.1,34.04 Q3.1 35.69,32.62 R4.2 C12.1
PD0
  Top 0.305: J4.4 60.2,38.61 59.83,38.98 IC2.30
  Bottom 0.305: J3.1 63.5,47.12 64.26,46.35 64.26,40.89 J4.4
PD1
  Top 0.305: J3.2 60.96,49.4 61.47,49.02 63.88,46.61 63.88,39.75 | J4.5 63.12,36.07 63.88,36.83 63.88,39.75 | IC2.31 60.18,39.48 60.58,39.88 63.75,39.88 63.88,39.75
PD2
  Top 0.305: IC2.32 57.34,39.98 58.42,41.05 58.42,41.27 58.42,41.53 J3.3
  Bottom 0.305: J3.3 58.42,49.53
PD3
  Top 0.305: J3.4 55.88,48.9 56.52,48.26 56.9,48.26 57.78,47.37 57.78,43.05 56.11,41.37 IC2.1
RESET  (via drill 0.61)
  Top 0.305: POWER.1 v33.02,8.76 | R1.1 47.75,29.72 47.75,32.92 IC1.3 46.23,32.24 v46.23,32 | v58.06,25.15 56.34,25.15 56.21,25.27 v54.48,25.27 54.48,27.18 49.78,27.18 R1.1 | IC2.29 58.55,38.48 v59.31,37.72 59.69,37.34 C23.1 | C3.1 47.37,27.81 48.13,28.57 R1.1
  Top 0.406: RESET2.1 RESET2.2 10.42,49.92 v10.41,49.4
  Bottom 0.305: v58.06,25.15 63.37,25.15 63.63,25.4 ICSP.5 64.26,25.4 65.53,26.67 67.18,26.67 67.44,26.92 67.44,31.24 66.93,31.75 65.91,31.75 62.87,34.8 60.07,34.8 59.82,35.05 59.82,37.21 v59.31,37.72 | v54.48,25.27 54.61,25.15 54.61,25.27 53.59,24.26 52.07,24.26 50.29,22.48 50.29,18.16 49.28,17.14 49.28,14.73 50.29,13.72 50.29,13.21 49.53,12.45 43.05,12.45 39.12,8.51 33.4,8.38 v33.02,8.76 | v10.41,49.4 10.67,49.15 11.3,49.15 12.76,47.69 19.49,47.69 23.88,43.31 23.88,39.62 25.91,37.59 43.05,37.59 45.09,35.56 45.09,33.15 v46.23,32
RESET_W
  Top 0.254: IC6.59 42.39,24.99 42.75,25.35
  Top 0.305: 42.75,25.35 42.75,28.27 45.13,30.65 IC1.2
RTS
  Top 0.406: C23.2 60.71,34.8 J4.6
RXIN
  Top 0.254: RN2.7 19.2,41.51 18.54,42.16 18.54,43.94 17.14,45.34 14.86,45.34 13.97,44.45 13.97,43.86 U$1.R2 16.13,42.8 16.83,42.1 16.83,39.43 19.05,37.21 19.05,34.42 19.56,33.91 23.88,33.91 27.81,29.97 27.81,23.62 28.05,23.39 IC6.6
RXIP
  Top 0.254: RN2.8 18.98,40.71 17.97,41.72 17.97,43.5 17.4,44.07 U$1.R1 16,43.52 16.43,43.52 17.4,42.55 17.4,39.75 19.68,37.47 19.68,34.67 19.94,34.42 24.13,34.42 28.32,30.23 28.32,24.13 28.66,23.79 IC6.5
RXLED  (via drill 0.61)
  Top 0.254: v4.57,35.69 4.57,35.56 1.4,32.38 1.4,28.29 RX.C | IC6.72 35.21,28.48 35.47,28.74 36.1,28.74 v36.32,28.83
  Bottom 0.254: v36.32,28.83 33.02,28.83 32.77,29.08 30.73,29.08 21.34,38.48 21.34,42.04 17.97,45.4 13.14,45.4 4.57,36.83 v4.57,35.69
SCK  (via drill 0.61)
  Top 0.254: IC6.30 35.61,14.42 36.2,13.84 v36.2,13.72 | v49.15,13.59 48.51,12.95 IC11.2
  Top 0.305: IC2.17 52.61,34.19 52.83,33.91 v52.83,33.78 52.83,30.35 v52.96,30.23
  Bottom 0.229: 49.02,26.16 49.02,25.02
  Bottom 0.254: v36.2,13.72 36.83,14.35 36.83,18.92 44.45,26.54 45.97,26.54 50.04,30.61 50.16,30.61 | v49.15,13.59 48.13,14.61 48.13,22.35 49.02,23.24 49.02,25.02 | 50.16,30.61 50.29,30.61 51.18,31.5 | v52.96,30.23 52.96,30.73 52.2,31.5 52.07,31.5 | 50.16,30.61 | 49.02,26.16 50.27,27.41 50.27,30.5
  Bottom 0.305: J1.6 28.96,46.48 29.72,45.72 40.64,45.72 50.8,35.56 51.18,35.56 52.83,33.91 v52.83,33.78 | ICSP.3 61.72,27.94 61.21,28.45 55.12,28.45 v52.96,30.23 | 51.18,31.5 52.07,31.5
  Bottom 0.406: 50.04,30.61 50.27,30.5
SCK3  (via drill 0.61)
  Top 0.254: v54.1,13.97 53.59,14.48 52.83,14.48 52.58,14.73 49.28,14.73 49.02,14.99 45.47,14.99 45,14.52 IC11.4
  Top 0.305: X2.5 63.16,14.65 v61.72,13.21
  Bottom 0.305: v54.1,13.97 60.96,13.97 v61.72,13.21
SD_CS  (via drill 0.61)
  Top 0.254: v49.28,18.54 48.77,18.03 48.77,17.53 48.26,17.02 IC12.2
  Top 0.305: J3.5 53.34,48.9 54.61,47.62 56.64,47.62 57.15,47.12 57.15,43.31 55.61,41.76 IC2.2 | v51.69,30.61 49.53,30.61 49.15,30.99 49.15,35.94 46.1,38.99 46.1,44.83 v45.47,45.47
  Bottom 0.305: v49.28,18.54 49.28,22.48 51.56,24.77 51.56,25.02 51.44,30.23 51.69,30.48 v51.69,30.61 | v45.47,45.47 50.8,45.47 53.34,48.01 J3.5
SEN
  Top 0.254: IC6.31 36.01,14.91 36.32,14.61 36.83,14.61 37.21,14.22 37.21,13.34 36.58,12.7 35.56,12.7 35.31,12.95 32,12.95 30.99,13.97 28.45,13.97 27.94,14.48 27.94,15.49 27.15,16.29 27.05,16.29 IC13.4
SEN3  (via drill 0.61)
  Top 0.254: v54.86,18.03 54.86,18.29 53.59,19.56 48.64,19.56 47.75,18.67 46.61,18.67 45.61,17.67 IC12.4
  Top 0.305: X2.2 62.65,17.95 61.47,16.76 v61.47,16.26
  Bottom 0.305: v61.47,16.26 56.64,16.26 v54.86,18.03
SPDLED  (via drill 0.61)
  Top 0.254: IC6.67 37.21,28.58 37.97,29.34 41.27,29.34 43.43,31.5 v43.43,32
  Bottom 0.254: v43.43,32 43.43,35.43 42.55,36.32 25.27,36.32 22.61,38.99 22.61,42.55 18.61,46.55 12.64,46.55 1.78,35.69 1.78,34.67
  Bottom 0.305: U$1.L2 1.78,34.67
SS  (via drill 0.61)
  Top 0.254: IC6.29 35.21,14.39 v34.8,13.97 31.75,13.97 29.97,15.75 IC13.2
  Top 0.305: J1.3 36.58,49.15 36.96,48.77 40.26,48.77 41.53,47.62 44.7,47.62 46.74,45.47 46.74,39.57 49.91,36.4 | 49.88,36.32 49.78,36.32 49.78,31.88 v50.04,31.62 | 49.88,36.32 49.91,36.32 | 49.88,36.32 49.89,37.16 50.21,37.48 IC2.14 | R11.2 24.38,18.8 24.77,18.41 25.4,18.41 26.16,17.65 27.18,17.65 27.69,17.14 27.69,16.51 28.45,15.75 IC13.2
  Top 0.61: 49.91,36.32 49.91,36.4
  Bottom 0.254: v50.04,31.62 49.53,31.62 48.64,30.73 48.64,29.97 45.85,27.18 44.32,27.18 36.18,19.04 36.18,15.35 v34.8,13.97
SW
  pour Top (no thermals): 17.91,7.24 22.1,7.24 22.1,8.64 31.24,8.64 31.24,10.92 29.97,12.19 20.83,12.19 20.83,10.67 19.3,10.67 19.3,8 17.91,8
TXLED  (via drill 0.61)
  Top 0.254: v35.18,29.72 34.8,29.34 34.8,27.21 IC6.73 | TX.C 1.49,24.35 v1.4,24.13
  Bottom 0.254: v35.18,29.72 31.11,29.72 21.97,38.73 21.97,42.29 18.29,45.97 12.89,45.97 2.92,36.01 2.92,33.78 1.14,32 1.14,24.38 v1.4,24.13
TXON
  Top 0.254: IC6.9 27.09,22.19 26.8,22.48 26.8,29.46 23.37,32.89 18.8,32.89 17.78,33.91 17.78,36.58 16.64,37.72 14.61,37.72 14.22,38.1 14.22,38.95 U$1.R4 12.32,40.26 11.18,41.4 11.18,43.69 14.1,46.61 17.91,46.61 19.68,44.83 19.68,43.56 20.14,43.11 RN2.5
TXOP
  Top 0.254: IC6.8 27.69,22.59 27.3,22.97 27.3,29.72 23.62,33.4 19.18,33.4 18.41,34.16 18.41,36.96 16.51,38.86 15.58,38.86 U$1.R5 14.48,39.96 14.48,40.64 13.72,41.4 12.19,41.4 11.68,41.91 11.68,43.43 12.45,44.2 12.7,44.2 14.48,45.97 17.53,45.97 19.11,44.39 19.11,42.61 19.41,42.31 RN2.6
V1+
  Bottom 0.508: ZZ1.P$1 2.16,22.73 4.45,25.02 6.73,25.02 12.91,31.2 U$1.R10
V1-
  Bottom 0.508: ZZ1.P$2 4.69,22.73 6.1,24.13 7.24,24.13 15.37,32.26 15.37,33.82 U$1.R9
V2+
  Bottom 0.508: U$1.R7 17.02,36.45 17.65,35.81 17.65,31.62 10.79,24.77 10.79,23.92 ZZ1.P$4
V2-  (1 unrouted)
  Bottom 0.508: U$1.R8 16.76,35.18 16.76,32.26 7.87,23.37 7.75,23.37 7.23,22.84
VIN  (via drill 0.61)
  Top 0.406: C15.2 R8.1 46.86,24.64 ZZ1.P$8
  Top 0.61: R5.1 15.93,4.95 16.23,4.67 C11.+ 17.14,4.8 IC5.5
  Top 0.813: v10.16,12.7 10.16,10.79 11.68,8.89 X1.2 13.97,6.02 13.97,5.59 14.48,5.21 14.73,5.21 R5.1 | POWER.6 45.72,6.6 43.18,9.14 40.02,9.14 C14.+ v40.15,11.43 | D1.C 13.61,20.07 IC4.3 11.51,19.96 v11.43,20.04
  Bottom 0.813: 40.13,11.43 38.1,9.4 34.16,9.4 31.62,11.94 31.62,13.84 29.97,15.49 25.78,15.49 20.83,20.32 11.71,20.32 v11.43,20.04 11.43,14.86 10.16,13.46 v10.16,12.7
  Bottom 1.27: v40.15,11.43 40.13,11.43 40.64,11.68 42.67,13.72 46.99,13.72 46.99,22.86 47.77,23.64 ZZ1.P$8
WOL/IO
  Top 0.305: IC2.12 50.04,38.48 48.01,40.51 48.01,46.23 45.34,48.9 42.8,48.9 41.66,50.04 J1.1
XTAL1
  Top 0.305: IC2.7 53.11,40.87 53.09,40.89 53.09,42.16 53.32,42.4 Y1.3
XTAL2
  Top 0.305: 51.43,44.98 Y1.1 51.31,45.07 51.31,41.78 52.61,40.48 IC2.8

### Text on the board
Top: Arduino(TM) Ethernet Rev 8d | LC | Reference Designs ARE PROVIDED "AS IS" AND "WITH ALL FAULTS. Arduino DISCLAIMS ALL OTHER WARRANTIES, EXPRESS OR IMPLIED, | REGARDING PRODUCTS, INCLUDING BUT NOT LIMITED TO, ANY IMPLIED WARRANTIES OF MERCHANTABILITY OR FITNESS FOR A PARTICULAR PURPOSE | Arduino may make changes to specifications and product descriptions at any time, without notice. The Customer must not | rely on the absence or characteristics of any features or instructions marked "reserved" or "undefined." Arduino reserves | these for future definition and shall have no responsibility whatsoever for conflicts or incompatibilities arising from future changes to them. | The product information on the Web Site or Materials is subject to change without notice. Do not finalize a design with this information. | "ARDUINO" is a registered trademark.
Bottom: LS | in Italy | Made | ETH 8d
tPlace: S P I | DIGITAL | BLK | LINK | Ethernet-V8c | 100M
tNames: M.Banzi | D.Cuartielles | T.Igoe | G.Martino | 3 2 1 0 9 8 | AREF | GND | 7 6 5 4 3 2 1 0 | D.Mellis | 1 1 1 1 | * | * | * | TX | RX | * | * | * | (*=PWM) | TM | Arduino | www.arduino.cc | 1 | ANALOG IN | RES | 3V3 | 5V Gnd 12V | 0 1 2 3 4 5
